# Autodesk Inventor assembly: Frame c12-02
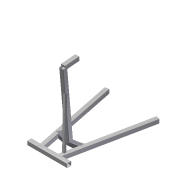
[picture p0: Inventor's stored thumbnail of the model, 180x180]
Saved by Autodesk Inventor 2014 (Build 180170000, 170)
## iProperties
Created: 2011-01
Part Number: Frame c12-02
Document SubType Name: Assembly
Designer: Thom Tremblay
_FrameDoc: Frame Assembly
_Version: 15.0.0
Author: Thom Tremblay
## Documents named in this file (16)
- C:\Inventor 2014 Essentials\Assemblies\Chapter 12\Frame\Frame c12-02.iam
- C:\Inventor 2014 Essentials\Assemblies\Chapter 12\Frame\Skeleton-c12-02.ipt
- C:\Inventor 2014 Essentials\Assemblies\Chapter 12\Frame\ANSI 3x3x3_16 00000001.ipt
- ANSI 3x3x3_16 00000001.ipt
- C:\Inventor 2014 Essentials\Assemblies\Chapter 12\Frame\ANSI 3x3x3_16 00000002.ipt
- ANSI 3x3x3_16 00000002.ipt
- C:\Inventor 2014 Essentials\Assemblies\Chapter 12\Frame\ANSI 3x3x3_16 00000004.ipt
- ANSI 3x3x3_16 00000004.ipt
- C:\Inventor 2014 Essentials\Assemblies\Chapter 12\Frame\ANSI 3x3x3_16 00000005.ipt
- ANSI 3x3x3_16 00000005.ipt
- C:\Inventor 2014 Essentials\Assemblies\Chapter 12\Frame\ANSI 3x3x3_16 00000006.ipt
- ANSI 3x3x3_16 00000006.ipt
- C:\Inventor 2014 Essentials\Assemblies\Chapter 12\Frame\ANSI L 1.5 x 1.5 x 3_16 00000007.ipt
- ANSI L 1.5 x 1.5 x 3_16 00000007.ipt
- C:\Inventor 2014 Essentials\Assemblies\Chapter 12\Frame\ANSI 3x3x3_16 00000055.ipt
- ANSI 3x3x3_16 00000055.ipt
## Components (8 placed, 8 different names)
1. Frame Reference Model
2. ANSI 3x3x3_16 00000001:1
3. ANSI 3x3x3_16 00000002:1
4. ANSI 3x3x3_16 00000004:1
5. ANSI 3x3x3_16 00000005:1
6. ANSI 3x3x3_16 00000006:1
7. ANSI L 1.5 x 1.5 x 3_16 00000007:1
8. ANSI 3x3x3_16 00000055:1
